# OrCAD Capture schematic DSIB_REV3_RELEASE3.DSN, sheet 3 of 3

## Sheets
3 Connectors: size Custom; title: dSIB; company: Intuitive Surgical, Inc.; note: TBD; note: 1266 Kifer Road; note: Sunnyvale, CA 94086
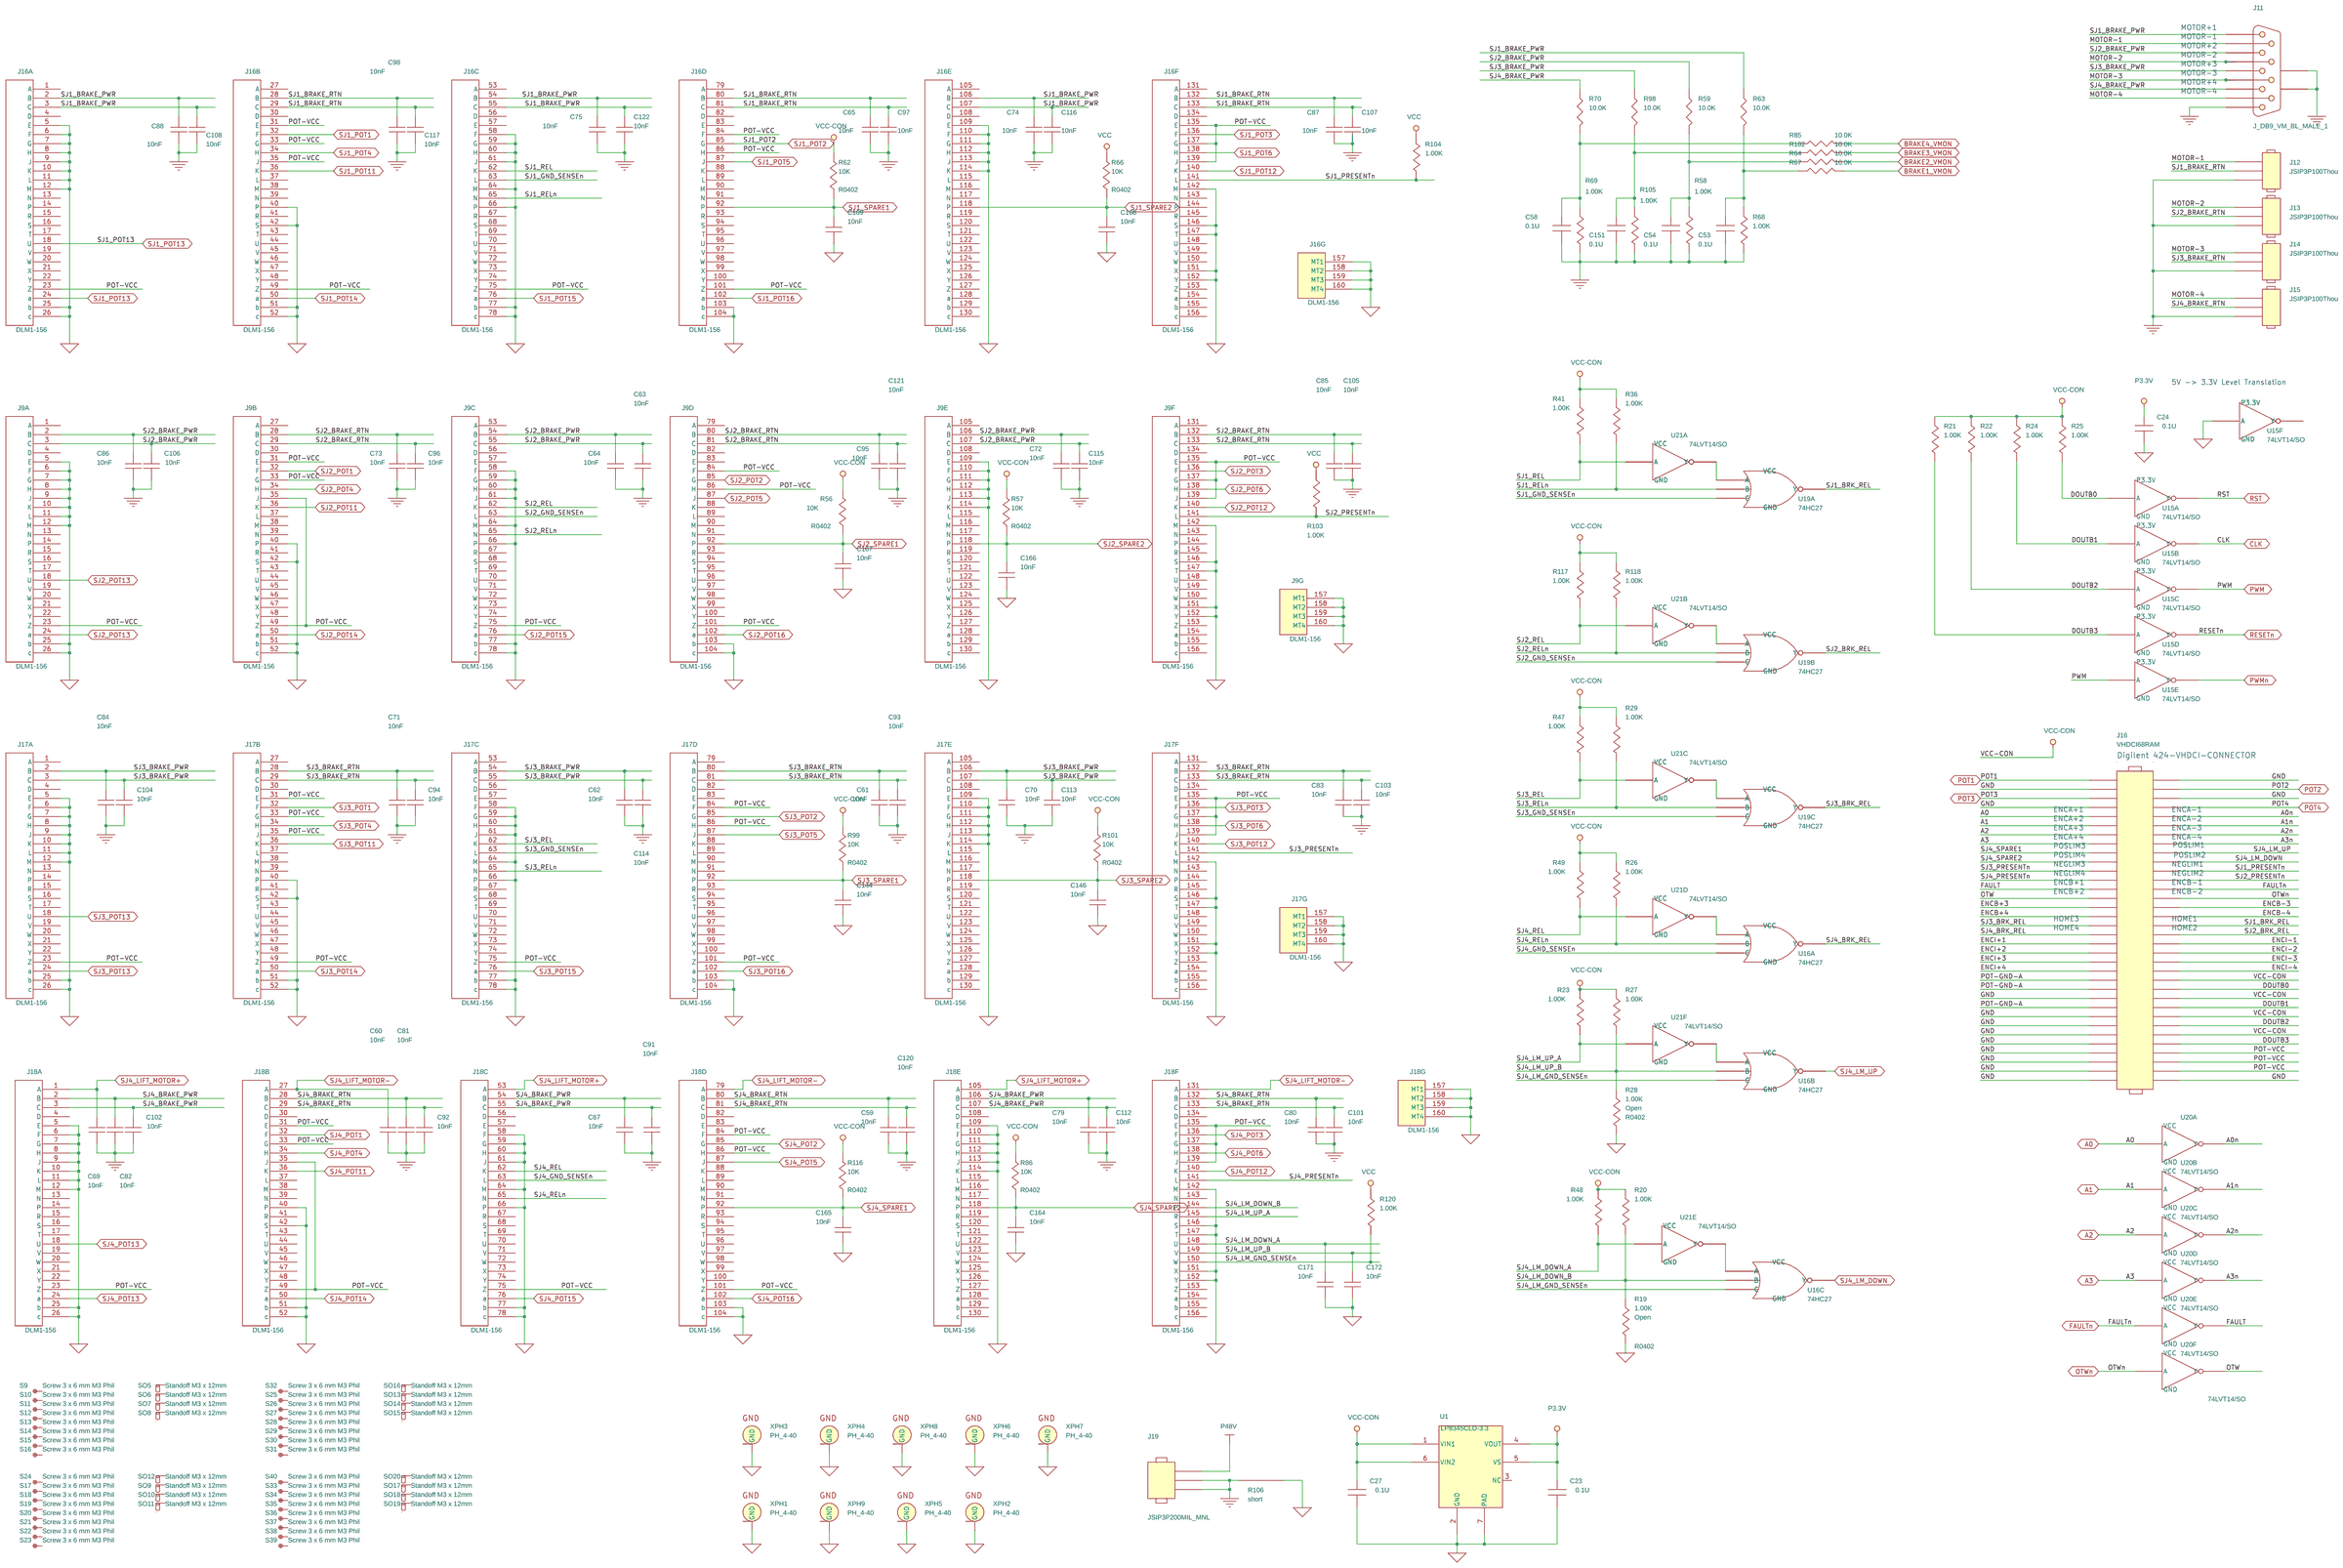
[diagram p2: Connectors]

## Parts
C23  0.1U  [C0402]
C24  0.1U  [C0402]
C27  0.1U  [C0402]
C53  0.1U  [C0402]
C54  0.1U  [C0402]
C58  0.1U  [C0402]
C59  10nF  [C0402]
C60  10nF  [C0402]
C61  10nF  [C0402]
C62  10nF  [C0402]
C63  10nF  [C0402]
C64  10nF  [C0402]
C65  10nF  [C0402]
C67  10nF  [C0402]
C69  10nF  [C0402]
C70  10nF  [C0402]
C71  10nF  [C0402]
C72  10nF  [C0402]
C73  10nF  [C0402]
C74  10nF  [C0402]
C75  10nF  [C0402]
C79  10nF  [C0402]
C80  10nF  [C0402]
C81  10nF  [C0402]
C82  10nF  [C0402]
C83  10nF  [C0402]
C84  10nF  [C0402]
C85  10nF  [C0402]
C86  10nF  [C0402]
C87  10nF  [C0402]
C88  10nF  [C0402]
C91  10nF  [C0402]
C92  10nF  [C0402]
C93  10nF  [C0402]
C94  10nF  [C0402]
C95  10nF  [C0402]
C96  10nF  [C0402]
C97  10nF  [C0402]
C98  10nF  [C0402]
C101  10nF  [C0402]
C102  10nF  [C0402]
C103  10nF  [C0402]
C104  10nF  [C0402]
C105  10nF  [C0402]
C106  10nF  [C0402]
C107  10nF  [C0402]
C108  10nF  [C0402]
C112  10nF  [C0402]
C113  10nF  [C0402]
C114  10nF  [C0402]
C115  10nF  [C0402]
C116  10nF  [C0402]
C117  10nF  [C0402]
C120  10nF  [C0402]
C121  10nF  [C0402]
C122  10nF  [C0402]
C144  10nF  [C0402]
C146  10nF  [C0402]
C151  0.1U  [C0402]
C164  10nF  [C0402]
C165  10nF  [C0402]
C166  10nF  [C0402]
C167  10nF  [C0402]
C168  10nF  [C0402]
C169  10nF  [C0402]
C171  10nF  [C0402]
C172  10nF  [C0402]
J9  DLM1-156  [DLM1-156]  (sections A,B,C,D,E,F,G)
J11  J_DB9_VM_BL_MALE_1  [DB9M]
J12  JSIP3P100Thou  [JSIP3P2.54MM]
J13  JSIP3P100Thou  [JSIP3P2.54MM]
J14  JSIP3P100Thou  [JSIP3P2.54MM]
J15  JSIP3P100Thou  [JSIP3P2.54MM]
J16  DLM1-156  [DLM1-156]  (sections A,B,C,D,E,F,G)
J17  DLM1-156  [DLM1-156]  (sections A,B,C,D,E,F,G)
J18  DLM1-156  [DLM1-156]  (sections A,B,C,D,E,F,G)
J19  JSIP3P200MIL_MNL  [TB-3/5.08]
R19  1.00K  [R0402]
R20  1.00K  [RESC1005_IS0402N]
R21  1.00K  [RESC1005_IS0402N]
R22  1.00K  [RESC1005_IS0402N]
R23  1.00K  [RESC1005_IS0402N]
R24  1.00K  [RESC1005_IS0402N]
R25  1.00K  [RESC1005_IS0402N]
R26  1.00K  [RESC1005_IS0402N]
R27  1.00K  [RESC1005_IS0402N]
R28  1.00K  [R0402]
R29  1.00K  [RESC1005_IS0402N]
R36  1.00K  [RESC1005_IS0402N]
R41  1.00K  [RESC1005_IS0402N]
R47  1.00K  [RESC1005_IS0402N]
R48  1.00K  [RESC1005_IS0402N]
R49  1.00K  [RESC1005_IS0402N]
R56  10K  [R0402]
R57  10K  [R0402]
R58  1.00K  [RESC1005_IS0402N]
R59  10.0K  [R0402]
R62  10K  [R0402]
R63  10.0K  [R0402]
R64  10.0K  [R0402]
R66  10K  [R0402]
R67  10.0K  [R0402]
R68  1.00K  [RESC1005_IS0402N]
R69  1.00K  [RESC1005_IS0402N]
R70  10.0K  [R0402]
R85  10.0K  [R0402]
R86  10K  [R0402]
R98  10.0K  [R0402]
R99  10K  [R0402]
R101  10K  [R0402]
R102  10.0K  [R0402]
R103  1.00K  [RESC1005_IS0402N]
R104  1.00K  [RESC1005_IS0402N]
R105  1.00K  [RESC1005_IS0402N]
R106  short  [S1210]
R116  10K  [R0402]
R117  1.00K  [RESC1005_IS0402N]
R118  1.00K  [RESC1005_IS0402N]
R120  1.00K  [RESC1005_IS0402N]
S9  Screw 3 x 6 mm M3 Phil  [TH825]
S10  Screw 3 x 6 mm M3 Phil  [TH825]
S11  Screw 3 x 6 mm M3 Phil  [TH825]
S12  Screw 3 x 6 mm M3 Phil  [TH825]
S13  Screw 3 x 6 mm M3 Phil  [TH825]
S14  Screw 3 x 6 mm M3 Phil  [TH825]
S15  Screw 3 x 6 mm M3 Phil  [TH825]
S16  Screw 3 x 6 mm M3 Phil  [TH825]
S17  Screw 3 x 6 mm M3 Phil  [TH825]
S18  Screw 3 x 6 mm M3 Phil  [TH825]
S19  Screw 3 x 6 mm M3 Phil  [TH825]
S20  Screw 3 x 6 mm M3 Phil  [TH825]
S21  Screw 3 x 6 mm M3 Phil  [TH825]
S22  Screw 3 x 6 mm M3 Phil  [TH825]
S23  Screw 3 x 6 mm M3 Phil  [TH825]
S24  Screw 3 x 6 mm M3 Phil  [TH825]
S25  Screw 3 x 6 mm M3 Phil  [TH825]
S26  Screw 3 x 6 mm M3 Phil  [TH825]
S27  Screw 3 x 6 mm M3 Phil  [TH825]
S28  Screw 3 x 6 mm M3 Phil  [TH825]
S29  Screw 3 x 6 mm M3 Phil  [TH825]
S30  Screw 3 x 6 mm M3 Phil  [TH825]
S31  Screw 3 x 6 mm M3 Phil  [TH825]
S32  Screw 3 x 6 mm M3 Phil  [TH825]
S33  Screw 3 x 6 mm M3 Phil  [TH825]
S34  Screw 3 x 6 mm M3 Phil  [TH825]
S35  Screw 3 x 6 mm M3 Phil  [TH825]
S36  Screw 3 x 6 mm M3 Phil  [TH825]
S37  Screw 3 x 6 mm M3 Phil  [TH825]
S38  Screw 3 x 6 mm M3 Phil  [TH825]
S39  Screw 3 x 6 mm M3 Phil  [TH825]
S40  Screw 3 x 6 mm M3 Phil  [TH825]
SO5  Standoff M3 x 12mm  [TH40Thou]
SO6  Standoff M3 x 12mm  [TH40Thou]
SO7  Standoff M3 x 12mm  [TH40Thou]
SO8  Standoff M3 x 12mm  [TH40Thou]
SO9  Standoff M3 x 12mm  [TH40Thou]
SO10  Standoff M3 x 12mm  [TH40Thou]
SO11  Standoff M3 x 12mm  [TH40Thou]
SO12  Standoff M3 x 12mm  [TH40Thou]
SO13  Standoff M3 x 12mm  [TH40Thou]
SO14  Standoff M3 x 12mm  [TH40Thou]
SO15  Standoff M3 x 12mm  [TH40Thou]
SO16  Standoff M3 x 12mm  [TH40Thou]
SO17  Standoff M3 x 12mm  [TH40Thou]
SO18  Standoff M3 x 12mm  [TH40Thou]
SO19  Standoff M3 x 12mm  [TH40Thou]
SO20  Standoff M3 x 12mm  [TH40Thou]
U1  LP8345CLD-3.3  [LLP6]
U15  74LVT14/SO  [TSSOP14]  (sections A,B,C,D,E,F)
U16  74HC27  [DHVQFN14]  (sections A,B,C)
U19  74HC27  [DHVQFN14]  (sections A,B,C)
U20  74LVT14/SO  [TSSOP14]  (sections A,B,C,D,E,F)
U21  74LVT14/SO  [TSSOP14]  (sections A,B,C,D,E,F)
XPH1  PH_4-40  [MTG120P]
XPH2  PH_4-40  [MTG120P]
XPH3  PH_4-40  [MTG120P]
XPH4  PH_4-40  [MTG120P]
XPH5  PH_4-40  [MTG120P]
XPH6  PH_4-40  [MTG120P]
XPH7  PH_4-40  [MTG120P]
XPH8  PH_4-40  [MTG120P]
XPH9  PH_4-40  [MTG120P]

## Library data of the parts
C23 = C_100nF_10%_50V_X7R_0: COMPFIXED: NO; COMPGROUP: 0; COMPHEIGHT: 0.000; COMPKEY: NO; COMPLOC: [6693.000,6327.000]; COMPLOCKED: NO; COMPROT: 180; COMPSIDE: BOT; DECOUPLER: NO; MEMORY: NO
C24 = C_100nF_10%_50V_X7R_0: COMPFIXED: NO; COMPGROUP: 0; COMPHEIGHT: 0.000; COMPKEY: NO; COMPLOC: [4590.000,6330.000]; COMPLOCKED: NO; COMPROT: 0; COMPSIDE: BOT; DECOUPLER: NO; FPLIST: C0603; MEMORY: NO
C27 = C_100nF_10%_50V_X7R_0: COMPFIXED: NO; COMPGROUP: 0; COMPHEIGHT: 0.000; COMPKEY: NO; COMPLOC: [6750.000,6096.000]; COMPLOCKED: NO; COMPROT: 0; COMPSIDE: BOT; DECOUPLER: NO; MEMORY: NO
C53 = C_100nF_10%_50V_X7R_0: COMPFIXED: NO; COMPGROUP: 0; COMPHEIGHT: 0.000; COMPKEY: NO; COMPLOC: [677.000,5735.000]; COMPLOCKED: NO; COMPROT: 0; COMPSIDE: BOT; DECOUPLER: NO; MEMORY: NO
C54 = C_100nF_10%_50V_X7R_0: COMPFIXED: NO; COMPGROUP: 0; COMPHEIGHT: 0.000; COMPKEY: NO; COMPLOC: [2005.000,5690.000]; COMPLOCKED: NO; COMPROT: 0; COMPSIDE: BOT; DECOUPLER: NO; MEMORY: NO
C58 = C_100nF_10%_50V_X7R_0: COMPFIXED: NO; COMPGROUP: 0; COMPHEIGHT: 0.000; COMPKEY: NO; COMPLOC: [5262.000,5310.000]; COMPLOCKED: NO; COMPROT: 0; COMPSIDE: BOT; DECOUPLER: NO; MEMORY: NO
C59 C144 C146 C164-C169 C171 C172 = C_10nF_100V_X7R_3: COMPFIXED: NO; COMPGROUP: 0; COMPHEIGHT: 0.000; COMPKEY: NO; COMPLOC: [4820.000,5170.000]; COMPLOCKED: NO; COMPROT: 180; COMPSIDE: BOT; DECOUPLER: NO; FPLIST: C0805; MEMORY: NO
C60 = C_10nF_100V_X7R_3: COMPFIXED: NO; COMPGROUP: 0; COMPHEIGHT: 0.000; COMPKEY: NO; COMPLOC: [4452.000,5172.000]; COMPLOCKED: NO; COMPROT: 0; COMPSIDE: BOT; DECOUPLER: NO; FPLIST: C0805; MEMORY: NO
C61 = C_10nF_100V_X7R_3: COMPFIXED: NO; COMPGROUP: 0; COMPHEIGHT: 0.000; COMPKEY: NO; COMPLOC: [3492.000,5178.000]; COMPLOCKED: NO; COMPROT: 0; COMPSIDE: BOT; DECOUPLER: NO; FPLIST: C0805; MEMORY: NO
C62 = C_10nF_100V_X7R_3: COMPFIXED: NO; COMPGROUP: 0; COMPHEIGHT: 0.000; COMPKEY: NO; COMPLOC: [3294.000,5178.000]; COMPLOCKED: NO; COMPROT: 0; COMPSIDE: BOT; DECOUPLER: NO; FPLIST: C0805; MEMORY: NO
C63 = C_10nF_100V_X7R_3: COMPFIXED: NO; COMPGROUP: 0; COMPHEIGHT: 0.000; COMPKEY: NO; COMPLOC: [2190.000,5148.000]; COMPLOCKED: NO; COMPROT: 270; COMPSIDE: BOT; DECOUPLER: NO; FPLIST: C0805; MEMORY: NO
C64 = C_10nF_100V_X7R_3: COMPFIXED: NO; COMPGROUP: 0; COMPHEIGHT: 0.000; COMPKEY: NO; COMPLOC: [2088.000,5148.000]; COMPLOCKED: NO; COMPROT: 270; COMPSIDE: BOT; DECOUPLER: NO; FPLIST: C0805; MEMORY: NO
C65 C74 C87 C88 C97 C107 C116 = C_10nF_100V_X7R_3: COMPFIXED: NO; COMPGROUP: 0; COMPHEIGHT: 0.000; COMPKEY: NO; COMPLOC: [675.000,4923.000]; COMPLOCKED: NO; COMPROT: 0; COMPSIDE: BOT; DECOUPLER: NO; MEMORY: NO
C67 = C_10nF_100V_X7R_3: COMPFIXED: NO; COMPGROUP: 0; COMPHEIGHT: 0.000; COMPKEY: NO; COMPLOC: [4182.000,5075.000]; COMPLOCKED: NO; COMPROT: 0; COMPSIDE: BOT; DECOUPLER: NO; FPLIST: C0805; MEMORY: NO
C69 = C_10nF_100V_X7R_3: COMPFIXED: NO; COMPGROUP: 0; COMPHEIGHT: 0.000; COMPKEY: NO; COMPLOC: [4182.000,5022.000]; COMPLOCKED: NO; COMPROT: 0; COMPSIDE: BOT; DECOUPLER: NO; FPLIST: C0805; MEMORY: NO
C70 = C_10nF_100V_X7R_3: COMPFIXED: NO; COMPGROUP: 0; COMPHEIGHT: 0.000; COMPKEY: NO; COMPLOC: [3768.000,4974.000]; COMPLOCKED: NO; COMPROT: 180; COMPSIDE: BOT; DECOUPLER: NO; FPLIST: C0805; MEMORY: NO
C71 = C_10nF_100V_X7R_3: COMPFIXED: NO; COMPGROUP: 0; COMPHEIGHT: 0.000; COMPKEY: NO; COMPLOC: [3048.000,4986.000]; COMPLOCKED: NO; COMPROT: 0; COMPSIDE: BOT; DECOUPLER: NO; FPLIST: C0805; MEMORY: NO
C72 = C_10nF_100V_X7R_3: COMPFIXED: NO; COMPGROUP: 0; COMPHEIGHT: 0.000; COMPKEY: NO; COMPLOC: [2520.000,4974.000]; COMPLOCKED: NO; COMPROT: 180; COMPSIDE: BOT; DECOUPLER: NO; FPLIST: C0805; MEMORY: NO
C73 = C_10nF_100V_X7R_3: COMPFIXED: NO; COMPGROUP: 0; COMPHEIGHT: 0.000; COMPKEY: NO; COMPLOC: [1794.000,4974.000]; COMPLOCKED: NO; COMPROT: 0; COMPSIDE: BOT; DECOUPLER: NO; FPLIST: C0805; MEMORY: NO
C75 = C_10nF_100V_X7R_3: COMPFIXED: NO; COMPGROUP: 0; COMPHEIGHT: 0.000; COMPKEY: NO; COMPLOC: [675.000,4977.000]; COMPLOCKED: NO; COMPROT: 0; COMPSIDE: BOT; DECOUPLER: NO; MEMORY: NO
C79 = C_10nF_100V_X7R_3: COMPFIXED: NO; COMPGROUP: 0; COMPHEIGHT: 0.000; COMPKEY: NO; COMPLOC: [4950.000,4968.000]; COMPLOCKED: NO; COMPROT: 180; COMPSIDE: BOT; DECOUPLER: NO; FPLIST: C0805; MEMORY: NO
C80 = C_10nF_100V_X7R_3: COMPFIXED: NO; COMPGROUP: 0; COMPHEIGHT: 0.000; COMPKEY: NO; COMPLOC: [4950.000,4920.000]; COMPLOCKED: NO; COMPROT: 180; COMPSIDE: BOT; DECOUPLER: NO; FPLIST: C0805; MEMORY: NO
C81 = C_10nF_100V_X7R_3: COMPFIXED: NO; COMPGROUP: 0; COMPHEIGHT: 0.000; COMPKEY: NO; COMPLOC: [4182.000,4968.000]; COMPLOCKED: NO; COMPROT: 0; COMPSIDE: BOT; DECOUPLER: NO; FPLIST: C0805; MEMORY: NO
C82 = C_10nF_100V_X7R_3: COMPFIXED: NO; COMPGROUP: 0; COMPHEIGHT: 0.000; COMPKEY: NO; COMPLOC: [4182.000,4920.000]; COMPLOCKED: NO; COMPROT: 0; COMPSIDE: BOT; DECOUPLER: NO; FPLIST: C0805; MEMORY: NO
C83 = C_10nF_100V_X7R_3: COMPFIXED: NO; COMPGROUP: 0; COMPHEIGHT: 0.000; COMPKEY: NO; COMPLOC: [3768.000,4920.000]; COMPLOCKED: NO; COMPROT: 180; COMPSIDE: BOT; DECOUPLER: NO; FPLIST: C0805; MEMORY: NO
C84 = C_10nF_100V_X7R_3: COMPFIXED: NO; COMPGROUP: 0; COMPHEIGHT: 0.000; COMPKEY: NO; COMPLOC: [3048.000,4932.000]; COMPLOCKED: NO; COMPROT: 0; COMPSIDE: BOT; DECOUPLER: NO; FPLIST: C0805; MEMORY: NO
C85 = C_10nF_100V_X7R_3: COMPFIXED: NO; COMPGROUP: 0; COMPHEIGHT: 0.000; COMPKEY: NO; COMPLOC: [2520.000,4920.000]; COMPLOCKED: NO; COMPROT: 180; COMPSIDE: BOT; DECOUPLER: NO; FPLIST: C0805; MEMORY: NO
C86 = C_10nF_100V_X7R_3: COMPFIXED: NO; COMPGROUP: 0; COMPHEIGHT: 0.000; COMPKEY: NO; COMPLOC: [1794.000,4920.000]; COMPLOCKED: NO; COMPROT: 0; COMPSIDE: BOT; DECOUPLER: NO; FPLIST: C0805; MEMORY: NO
C91 = C_10nF_100V_X7R_3: COMPFIXED: NO; COMPGROUP: 0; COMPHEIGHT: 0.000; COMPKEY: NO; COMPLOC: [4950.000,4872.000]; COMPLOCKED: NO; COMPROT: 180; COMPSIDE: BOT; DECOUPLER: NO; FPLIST: C0805; MEMORY: NO
C92 = C_10nF_100V_X7R_3: COMPFIXED: NO; COMPGROUP: 0; COMPHEIGHT: 0.000; COMPKEY: NO; COMPLOC: [4182.000,4872.000]; COMPLOCKED: NO; COMPROT: 0; COMPSIDE: BOT; DECOUPLER: NO; FPLIST: C0805; MEMORY: NO
C93 = C_10nF_100V_X7R_3: COMPFIXED: NO; COMPGROUP: 0; COMPHEIGHT: 0.000; COMPKEY: NO; COMPLOC: [3768.000,4872.000]; COMPLOCKED: NO; COMPROT: 180; COMPSIDE: BOT; DECOUPLER: NO; FPLIST: C0805; MEMORY: NO
C94 = C_10nF_100V_X7R_3: COMPFIXED: NO; COMPGROUP: 0; COMPHEIGHT: 0.000; COMPKEY: NO; COMPLOC: [3048.000,4878.000]; COMPLOCKED: NO; COMPROT: 0; COMPSIDE: BOT; DECOUPLER: NO; FPLIST: C0805; MEMORY: NO
C95 = C_10nF_100V_X7R_3: COMPFIXED: NO; COMPGROUP: 0; COMPHEIGHT: 0.000; COMPKEY: NO; COMPLOC: [2520.000,4866.000]; COMPLOCKED: NO; COMPROT: 180; COMPSIDE: BOT; DECOUPLER: NO; FPLIST: C0805; MEMORY: NO
C96 = C_10nF_100V_X7R_3: COMPFIXED: NO; COMPGROUP: 0; COMPHEIGHT: 0.000; COMPKEY: NO; COMPLOC: [1794.000,4872.000]; COMPLOCKED: NO; COMPROT: 0; COMPSIDE: BOT; DECOUPLER: NO; FPLIST: C0805; MEMORY: NO
C98 = C_10nF_100V_X7R_3: COMPFIXED: NO; COMPGROUP: 0; COMPHEIGHT: 0.000; COMPKEY: NO; COMPLOC: [675.000,4869.000]; COMPLOCKED: NO; COMPROT: 0; COMPSIDE: BOT; DECOUPLER: NO; MEMORY: NO
C101 = C_10nF_100V_X7R_3: COMPFIXED: NO; COMPGROUP: 0; COMPHEIGHT: 0.000; COMPKEY: NO; COMPLOC: [4950.000,4818.000]; COMPLOCKED: NO; COMPROT: 180; COMPSIDE: BOT; DECOUPLER: NO; FPLIST: C0805; MEMORY: NO
C102 = C_10nF_100V_X7R_3: COMPFIXED: NO; COMPGROUP: 0; COMPHEIGHT: 0.000; COMPKEY: NO; COMPLOC: [4182.000,4818.000]; COMPLOCKED: NO; COMPROT: 0; COMPSIDE: BOT; DECOUPLER: NO; FPLIST: C0805; MEMORY: NO
C103 = C_10nF_100V_X7R_3: COMPFIXED: NO; COMPGROUP: 0; COMPHEIGHT: 0.000; COMPKEY: NO; COMPLOC: [3768.000,4818.000]; COMPLOCKED: NO; COMPROT: 180; COMPSIDE: BOT; DECOUPLER: NO; FPLIST: C0805; MEMORY: NO
C104 = C_10nF_100V_X7R_3: COMPFIXED: NO; COMPGROUP: 0; COMPHEIGHT: 0.000; COMPKEY: NO; COMPLOC: [3048.000,4824.000]; COMPLOCKED: NO; COMPROT: 0; COMPSIDE: BOT; DECOUPLER: NO; FPLIST: C0805; MEMORY: NO
C105 = C_10nF_100V_X7R_3: COMPFIXED: NO; COMPGROUP: 0; COMPHEIGHT: 0.000; COMPKEY: NO; COMPLOC: [2520.000,4812.000]; COMPLOCKED: NO; COMPROT: 180; COMPSIDE: BOT; DECOUPLER: NO; FPLIST: C0805; MEMORY: NO
C106 = C_10nF_100V_X7R_3: COMPFIXED: NO; COMPGROUP: 0; COMPHEIGHT: 0.000; COMPKEY: NO; COMPLOC: [1794.000,4818.000]; COMPLOCKED: NO; COMPROT: 0; COMPSIDE: BOT; DECOUPLER: NO; FPLIST: C0805; MEMORY: NO
C108 = C_10nF_100V_X7R_3: COMPFIXED: NO; COMPGROUP: 0; COMPHEIGHT: 0.000; COMPKEY: NO; COMPLOC: [675.000,4821.000]; COMPLOCKED: NO; COMPROT: 0; COMPSIDE: BOT; DECOUPLER: NO; MEMORY: NO
C112 = C_10nF_100V_X7R_3: COMPFIXED: NO; COMPGROUP: 0; COMPHEIGHT: 0.000; COMPKEY: NO; COMPLOC: [4950.000,4770.000]; COMPLOCKED: NO; COMPROT: 180; COMPSIDE: BOT; DECOUPLER: NO; FPLIST: C0805; MEMORY: NO
C113 = C_10nF_100V_X7R_3: COMPFIXED: NO; COMPGROUP: 0; COMPHEIGHT: 0.000; COMPKEY: NO; COMPLOC: [3768.000,4764.000]; COMPLOCKED: NO; COMPROT: 180; COMPSIDE: BOT; DECOUPLER: NO; FPLIST: C0805; MEMORY: NO
C114 = C_10nF_100V_X7R_3: COMPFIXED: NO; COMPGROUP: 0; COMPHEIGHT: 0.000; COMPKEY: NO; COMPLOC: [3048.000,4770.000]; COMPLOCKED: NO; COMPROT: 0; COMPSIDE: BOT; DECOUPLER: NO; FPLIST: C0805; MEMORY: NO
C115 = C_10nF_100V_X7R_3: COMPFIXED: NO; COMPGROUP: 0; COMPHEIGHT: 0.000; COMPKEY: NO; COMPLOC: [2520.000,4758.000]; COMPLOCKED: NO; COMPROT: 180; COMPSIDE: BOT; DECOUPLER: NO; FPLIST: C0805; MEMORY: NO
C117 = C_10nF_100V_X7R_3: COMPFIXED: NO; COMPGROUP: 0; COMPHEIGHT: 0.000; COMPKEY: NO; COMPLOC: [675.000,4765.000]; COMPLOCKED: NO; COMPROT: 0; COMPSIDE: BOT; DECOUPLER: NO; MEMORY: NO
C120 = C_10nF_100V_X7R_3: COMPFIXED: NO; COMPGROUP: 0; COMPHEIGHT: 0.000; COMPKEY: NO; COMPLOC: [4950.000,4668.000]; COMPLOCKED: NO; COMPROT: 180; COMPSIDE: BOT; DECOUPLER: NO; FPLIST: C0805; MEMORY: NO
C121 = C_10nF_100V_X7R_3: COMPFIXED: NO; COMPGROUP: 0; COMPHEIGHT: 0.000; COMPKEY: NO; COMPLOC: [2520.000,4704.000]; COMPLOCKED: NO; COMPROT: 180; COMPSIDE: BOT; DECOUPLER: NO; FPLIST: C0805; MEMORY: NO
C122 = C_10nF_100V_X7R_3: COMPFIXED: NO; COMPGROUP: 0; COMPHEIGHT: 0.000; COMPKEY: NO; COMPLOC: [672.000,4674.000]; COMPLOCKED: NO; COMPROT: 0; COMPSIDE: BOT; DECOUPLER: NO; MEMORY: NO
C151 = C_100nF_10%_50V_X7R_0: COMPFIXED: NO; COMPGROUP: 0; COMPHEIGHT: 0.000; COMPKEY: NO; COMPLOC: [5490.000,3960.000]; COMPLOCKED: NO; COMPROT: 180; COMPSIDE: BOT; DECOUPLER: NO; MEMORY: NO
J9 = DLM1-156_0: COMPFIXED: YES; COMPGROUP: 0; COMPHEIGHT: 0.000; COMPKEY: NO; COMPLOC: [2190.000,3498.000]; COMPLOCKED: NO; COMPROT: 270; COMPSIDE: TOP; DECOUPLER: NO; MEMORY: NO
J11 = J_DB9_VM_BL_MALE_1: COMPFIXED: YES; COMPGROUP: 0; COMPHEIGHT: 0.000; COMPKEY: NO; COMPLOC: [6000.000,6500.000]; COMPLOCKED: YES; COMPROT: 0; COMPSIDE: BOT; DECOUPLER: NO; FPLIST: DB9M48,DB9M; MEMORY: NO; Vendor P/N: 626-1020-ND
J12 J13 = JSIP3P100Thou: COMPFIXED: NO; COMPGROUP: 0; COMPHEIGHT: 0.000; COMPKEY: NO; COMPLOC: [6400.000,5900.000]; COMPLOCKED: NO; COMPROT: 90; COMPSIDE: TOP; DECOUPLER: NO; MEMORY: NO; MFG: Wurth; MFG P/N: 61300311121; Vendor P/N: 732-5316-ND
J14 = JSIP3P100Thou: COMPFIXED: NO; COMPGROUP: 0; COMPHEIGHT: 0.000; COMPKEY: NO; COMPLOC: [6500.000,5900.000]; COMPLOCKED: NO; COMPROT: 90; COMPSIDE: TOP; DECOUPLER: NO; MEMORY: NO; MFG: Wurth; MFG P/N: 61300311121; Vendor P/N: 732-5316-ND
J15 = JSIP3P100Thou: COMPFIXED: NO; COMPGROUP: 0; COMPHEIGHT: 0.000; COMPKEY: NO; COMPLOC: [6600.000,5900.000]; COMPLOCKED: NO; COMPROT: 90; COMPSIDE: TOP; DECOUPLER: NO; MEMORY: NO; MFG: Wurth; MFG P/N: 61300311121; Vendor P/N: 732-5316-ND
J16 = DLM1-156_0: COMPFIXED: YES; COMPGROUP: 0; COMPHEIGHT: 0.000; COMPKEY: NO; COMPLOC: [1000.000,3500.000]; COMPLOCKED: NO; COMPROT: 270; COMPSIDE: TOP; DECOUPLER: NO; FPLIST: DLM1-156_FIXED,DLM1-156; MEMORY: NO; MFG P/N: R-HI-008068-2
J17 = DLM1-156_0: COMPFIXED: YES; COMPGROUP: 0; COMPHEIGHT: 0.000; COMPKEY: NO; COMPLOC: [3390.000,3498.000]; COMPLOCKED: NO; COMPROT: 270; COMPSIDE: TOP; DECOUPLER: NO; FPLIST: DLM1-156_FIXED,DLM1-156; MEMORY: NO
J18 = DLM1-156_0: COMPFIXED: YES; COMPGROUP: 0; COMPHEIGHT: 0.000; COMPKEY: NO; COMPLOC: [4605.000,3495.000]; COMPLOCKED: NO; COMPROT: 270; COMPSIDE: TOP; DECOUPLER: NO; MEMORY: NO
J19 = JSIP_3P_200MIL_RAM_MNL: COMPFIXED: NO; COMPGROUP: 0; COMPHEIGHT: 0.000; COMPKEY: NO; COMPLOC: [6012.000,3780.000]; COMPLOCKED: NO; COMPROT: 0; COMPSIDE: TOP; DECOUPLER: NO; MEMORY: NO
R19 = R1K1%0402_0: COMPFIXED: NO; COMPGROUP: 0; COMPHEIGHT: 0.000; COMPKEY: NO; COMPLOC: [4120.000,6615.000]; COMPLOCKED: NO; COMPROT: 0; COMPSIDE: BOT; DECOUPLER: NO; ISI P/N: Open; MEMORY: NO
R20 = R1K1%0402_0: COMPFIXED: NO; COMPGROUP: 0; COMPHEIGHT: 0.000; COMPKEY: NO; COMPLOC: [3978.000,6565.000]; COMPLOCKED: NO; COMPROT: 180; COMPSIDE: BOT; DECOUPLER: NO; FPLIST: R0402; MEMORY: NO
R21 = R1K1%0402_0: COMPFIXED: NO; COMPGROUP: 0; COMPHEIGHT: 0.000; COMPKEY: NO; COMPLOC: [4678.000,6515.000]; COMPLOCKED: NO; COMPROT: 180; COMPSIDE: BOT; DECOUPLER: NO; FPLIST: R0402; MEMORY: NO
R22 = R1K1%0402_0: COMPFIXED: NO; COMPGROUP: 0; COMPHEIGHT: 0.000; COMPKEY: NO; COMPLOC: [4267.000,6495.000]; COMPLOCKED: NO; COMPROT: 0; COMPSIDE: BOT; DECOUPLER: NO; FPLIST: R0402; MEMORY: NO
R23 = R1K1%0402_0: COMPFIXED: NO; COMPGROUP: 0; COMPHEIGHT: 0.000; COMPKEY: NO; COMPLOC: [4678.000,6415.000]; COMPLOCKED: NO; COMPROT: 180; COMPSIDE: BOT; DECOUPLER: NO; FPLIST: R0402; MEMORY: NO
R24 = R1K1%0402_0: COMPFIXED: NO; COMPGROUP: 0; COMPHEIGHT: 0.000; COMPKEY: NO; COMPLOC: [4267.000,6440.000]; COMPLOCKED: NO; COMPROT: 0; COMPSIDE: BOT; DECOUPLER: NO; FPLIST: R0402; MEMORY: NO
R25 = R1K1%0402_0: COMPFIXED: NO; COMPGROUP: 0; COMPHEIGHT: 0.000; COMPKEY: NO; COMPLOC: [4267.000,6385.000]; COMPLOCKED: NO; COMPROT: 0; COMPSIDE: BOT; DECOUPLER: NO; FPLIST: R0402; MEMORY: NO
R26 = R1K1%0402_0: COMPFIXED: NO; COMPGROUP: 0; COMPHEIGHT: 0.000; COMPKEY: NO; COMPLOC: [4050.000,6322.000]; COMPLOCKED: NO; COMPROT: 90; COMPSIDE: BOT; DECOUPLER: NO; FPLIST: R0402; MEMORY: NO
R27 = R1K1%0402_0: COMPFIXED: NO; COMPGROUP: 0; COMPHEIGHT: 0.000; COMPKEY: NO; COMPLOC: [3995.000,6322.000]; COMPLOCKED: NO; COMPROT: 90; COMPSIDE: BOT; DECOUPLER: NO; FPLIST: R0402; MEMORY: NO
R28 = R1K1%0402_0: COMPFIXED: NO; COMPGROUP: 0; COMPHEIGHT: 0.000; COMPKEY: NO; COMPLOC: [3870.000,6320.000]; COMPLOCKED: NO; COMPROT: 180; COMPSIDE: BOT; DECOUPLER: NO; ISI P/N: Open; MEMORY: NO
R29 = R1K1%0402_0: COMPFIXED: NO; COMPGROUP: 0; COMPHEIGHT: 0.000; COMPKEY: NO; COMPLOC: [4312.000,6215.000]; COMPLOCKED: NO; COMPROT: 0; COMPSIDE: BOT; DECOUPLER: NO; FPLIST: R0402; MEMORY: NO
R36 R41 = R1K1%0402_0: COMPFIXED: NO; COMPGROUP: 0; COMPHEIGHT: 0.000; COMPKEY: NO; COMPLOC: [5113.000,5930.000]; COMPLOCKED: NO; COMPROT: 180; COMPSIDE: BOT; DECOUPLER: NO; FPLIST: R0402; MEMORY: NO
R47 = R1K1%0402_0: COMPFIXED: NO; COMPGROUP: 0; COMPHEIGHT: 0.000; COMPKEY: NO; COMPLOC: [5113.000,5835.000]; COMPLOCKED: NO; COMPROT: 180; COMPSIDE: BOT; DECOUPLER: NO; FPLIST: R0402; MEMORY: NO
R48 = R1K1%0402_0: COMPFIXED: NO; COMPGROUP: 0; COMPHEIGHT: 0.000; COMPKEY: NO; COMPLOC: [4697.000,5860.000]; COMPLOCKED: NO; COMPROT: 0; COMPSIDE: BOT; DECOUPLER: NO; FPLIST: R0402; MEMORY: NO
R49 = R1K1%0402_0: COMPFIXED: NO; COMPGROUP: 0; COMPHEIGHT: 0.000; COMPKEY: NO; COMPLOC: [4697.000,5805.000]; COMPLOCKED: NO; COMPROT: 0; COMPSIDE: BOT; DECOUPLER: NO; FPLIST: R0402; MEMORY: NO
R56 R57 R62 R66 R86 R99 R101 R116 = R10.0K1%0402_0: COMPFIXED: NO; COMPGROUP: 0; COMPHEIGHT: 0.000; COMPKEY: NO; COMPLOC: [2058.000,5802.000]; COMPLOCKED: NO; COMPROT: 180; COMPSIDE: BOT; DECOUPLER: NO; MEMORY: NO
R58 = R1K1%0402_0: COMPFIXED: NO; COMPGROUP: 0; COMPHEIGHT: 0.000; COMPKEY: NO; COMPLOC: [1963.000,5745.000]; COMPLOCKED: NO; COMPROT: 180; COMPSIDE: BOT; DECOUPLER: NO; MEMORY: NO
R59 = R_10K_1%_TF_0402: COMPFIXED: NO; COMPGROUP: 0; COMPHEIGHT: 0.000; COMPKEY: NO; COMPLOC: [1962.000,5802.000]; COMPLOCKED: NO; COMPROT: 180; COMPSIDE: BOT; DECOUPLER: NO; MEMORY: NO
R63 = R_10K_1%_TF_0402: COMPFIXED: NO; COMPGROUP: 0; COMPHEIGHT: 0.000; COMPKEY: NO; COMPLOC: [635.000,5795.000]; COMPLOCKED: NO; COMPROT: 180; COMPSIDE: BOT; DECOUPLER: NO; MEMORY: NO
R64 = R_10K_1%_TF_0402: COMPFIXED: NO; COMPGROUP: 0; COMPHEIGHT: 0.000; COMPKEY: NO; COMPLOC: [2058.000,5694.000]; COMPLOCKED: NO; COMPROT: 180; COMPSIDE: BOT; DECOUPLER: NO; MEMORY: NO
R67 = R_10K_1%_TF_0402: COMPFIXED: NO; COMPGROUP: 0; COMPHEIGHT: 0.000; COMPKEY: NO; COMPLOC: [786.000,5670.000]; COMPLOCKED: NO; COMPROT: 180; COMPSIDE: BOT; DECOUPLER: NO; MEMORY: NO
R68 = R1K1%0402_0: COMPFIXED: NO; COMPGROUP: 0; COMPHEIGHT: 0.000; COMPKEY: NO; COMPLOC: [633.000,5680.000]; COMPLOCKED: NO; COMPROT: 180; COMPSIDE: BOT; DECOUPLER: NO; MEMORY: NO
R69 = R1K1%0402_0: COMPFIXED: NO; COMPGROUP: 0; COMPHEIGHT: 0.000; COMPKEY: NO; COMPLOC: [5218.000,5360.000]; COMPLOCKED: NO; COMPROT: 180; COMPSIDE: BOT; DECOUPLER: NO; MEMORY: NO
R70 = R_10K_1%_TF_0402: COMPFIXED: NO; COMPGROUP: 0; COMPHEIGHT: 0.000; COMPKEY: NO; COMPLOC: [5262.000,5256.000]; COMPLOCKED: NO; COMPROT: 0; COMPSIDE: BOT; DECOUPLER: NO; MEMORY: NO
R85 = R_10K_1%_TF_0402: COMPFIXED: NO; COMPGROUP: 0; COMPHEIGHT: 0.000; COMPKEY: NO; COMPLOC: [5610.000,4590.000]; COMPLOCKED: NO; COMPROT: 0; COMPSIDE: BOT; DECOUPLER: NO; MEMORY: NO
R98 = R_10K_1%_TF_0402: COMPFIXED: NO; COMPGROUP: 0; COMPHEIGHT: 0.000; COMPKEY: NO; COMPLOC: [5493.000,4071.000]; COMPLOCKED: NO; COMPROT: 180; COMPSIDE: BOT; DECOUPLER: NO; MEMORY: NO
R102 = R_10K_1%_TF_0402: COMPFIXED: NO; COMPGROUP: 0; COMPHEIGHT: 0.000; COMPKEY: NO; COMPLOC: [5490.000,4014.000]; COMPLOCKED: NO; COMPROT: 180; COMPSIDE: BOT; DECOUPLER: NO; MEMORY: NO
R103 = R1K1%0402_0: COMPFIXED: NO; COMPGROUP: 0; COMPHEIGHT: 0.000; COMPKEY: NO; COMPLOC: [2513.000,4025.000]; COMPLOCKED: NO; COMPROT: 180; COMPSIDE: BOT; DECOUPLER: NO; FPLIST: R0402; MEMORY: NO
R104 = R1K1%0402_0: COMPFIXED: NO; COMPGROUP: 0; COMPHEIGHT: 0.000; COMPKEY: NO; COMPLOC: [1408.000,4025.000]; COMPLOCKED: NO; COMPROT: 180; COMPSIDE: BOT; DECOUPLER: NO; FPLIST: R0402; MEMORY: NO
R105 = R1K1%0402_0: COMPFIXED: NO; COMPGROUP: 0; COMPHEIGHT: 0.000; COMPKEY: NO; COMPLOC: [5532.000,3905.000]; COMPLOCKED: NO; COMPROT: 0; COMPSIDE: BOT; DECOUPLER: NO; MEMORY: NO
R106 = R_SHORT_1: COMPFIXED: NO; COMPGROUP: 0; COMPHEIGHT: 0.000; COMPKEY: NO; COMPLOC: [5612.500,3777.500]; COMPLOCKED: NO; COMPROT: 270; COMPSIDE: BOT; DECOUPLER: NO; MEMORY: NO
R117 = R1K1%0402_0: COMPFIXED: NO; COMPGROUP: 0; COMPHEIGHT: 0.000; COMPKEY: NO; COMPLOC: [3275.000,3312.000]; COMPLOCKED: NO; COMPROT: 90; COMPSIDE: BOT; DECOUPLER: NO; FPLIST: R0402; MEMORY: NO
R118 = R1K1%0402_0: COMPFIXED: NO; COMPGROUP: 0; COMPHEIGHT: 0.000; COMPKEY: NO; COMPLOC: [3220.000,3312.000]; COMPLOCKED: NO; COMPROT: 90; COMPSIDE: BOT; DECOUPLER: NO; FPLIST: R0402; MEMORY: NO
R120 = R1K1%0402_0: COMPFIXED: NO; COMPGROUP: 0; COMPHEIGHT: 0.000; COMPKEY: NO; COMPLOC: [4993.000,2575.000]; COMPLOCKED: NO; COMPROT: 180; COMPSIDE: BOT; DECOUPLER: NO; FPLIST: R0402; MEMORY: NO
S9-S40 = M3_1
SO5-SO20 = Standoff_M3_12mm_1
U1 = UREG_LP38691_3.3V_0.5A_LDO: COMPFIXED: NO; COMPGROUP: 0; COMPHEIGHT: 0.000; COMPKEY: NO; COMPLOC: [6762.000,6156.000]; COMPLOCKED: NO; COMPROT: 0; COMPSIDE: BOT; DECOUPLER: NO; MEMORY: NO
U15 = U_74LVT14_TSSOP14: COMPFIXED: NO; COMPGROUP: 0; COMPHEIGHT: 0.000; COMPKEY: NO; COMPLOC: [4359.000,6387.000]; COMPLOCKED: NO; COMPROT: 270; COMPSIDE: BOT; DECOUPLER: NO; MEMORY: NO
U16 = U_74HC27_DHVQFN14: COMPFIXED: NO; COMPGROUP: 0; COMPHEIGHT: 0.000; COMPKEY: NO; COMPLOC: [4038.000,6396.000]; COMPLOCKED: NO; COMPROT: 0; COMPSIDE: BOT; DECOUPLER: NO; MEMORY: NO
U19 = U_74HC27_DHVQFN14: COMPFIXED: NO; COMPGROUP: 0; COMPHEIGHT: 0.000; COMPKEY: NO; COMPLOC: [4374.000,6060.000]; COMPLOCKED: NO; COMPROT: 0; COMPSIDE: BOT; DECOUPLER: NO; MEMORY: NO
U20 = 74HCT14_0: COMPFIXED: NO; COMPGROUP: 0; COMPHEIGHT: 0.000; COMPKEY: NO; COMPLOC: [3355.000,6225.000]; COMPLOCKED: NO; COMPROT: 90; COMPSIDE: BOT; DECOUPLER: NO; MEMORY: NO
U21 = 74HCT14_0: COMPFIXED: NO; COMPGROUP: 0; COMPHEIGHT: 0.000; COMPKEY: NO; COMPLOC: [5022.000,5934.000]; COMPLOCKED: NO; COMPROT: 90; COMPSIDE: BOT; DECOUPLER: NO; MEMORY: NO
XPH1 = 135006_GND_Plated_Hole_120_mil: COMPFIXED: NO; COMPGROUP: 0; COMPHEIGHT: 0.000; COMPKEY: NO; COMPLOC: [318.000,6755.000]; COMPLOCKED: NO; COMPROT: 0; COMPSIDE: TOP; DECOUPLER: NO; MEMORY: NO
XPH2 = 135006_GND_Plated_Hole_120_mil: COMPFIXED: NO; COMPGROUP: 0; COMPHEIGHT: 0.000; COMPKEY: NO; COMPLOC: [1968.000,6755.000]; COMPLOCKED: NO; COMPROT: 0; COMPSIDE: TOP; DECOUPLER: NO; MEMORY: NO
XPH3 = 135006_GND_Plated_Hole_120_mil: COMPFIXED: NO; COMPGROUP: 0; COMPHEIGHT: 0.000; COMPKEY: NO; COMPLOC: [3968.000,6755.000]; COMPLOCKED: YES; COMPROT: 0; COMPSIDE: TOP; DECOUPLER: NO; MEMORY: NO
XPH4 = 135006_GND_Plated_Hole_120_mil: COMPFIXED: YES; COMPGROUP: 0; COMPHEIGHT: 0.000; COMPKEY: NO; COMPLOC: [5168.000,6755.000]; COMPLOCKED: YES; COMPROT: 0; COMPSIDE: TOP; DECOUPLER: NO; MEMORY: NO
XPH5 = 135006_GND_Plated_Hole_120_mil: COMPFIXED: YES; COMPGROUP: 0; COMPHEIGHT: 0.000; COMPKEY: NO; COMPLOC: [6818.000,6755.000]; COMPLOCKED: YES; COMPROT: 0; COMPSIDE: TOP; DECOUPLER: NO; MEMORY: NO
XPH6 = 135006_GND_Plated_Hole_120_mil: COMPFIXED: YES; COMPGROUP: 0; COMPHEIGHT: 0.000; COMPKEY: NO; COMPLOC: [318.000,4755.000]; COMPLOCKED: YES; COMPROT: 0; COMPSIDE: TOP; DECOUPLER: NO; MEMORY: NO
XPH7 = 135006_GND_Plated_Hole_120_mil: COMPFIXED: YES; COMPGROUP: 0; COMPHEIGHT: 0.000; COMPKEY: NO; COMPLOC: [6818.000,4705.000]; COMPLOCKED: YES; COMPROT: 0; COMPSIDE: TOP; DECOUPLER: NO; MEMORY: NO
XPH8 = 135006_GND_Plated_Hole_120_mil: COMPFIXED: YES; COMPGROUP: 0; COMPHEIGHT: 0.000; COMPKEY: NO; COMPLOC: [318.000,2355.000]; COMPLOCKED: YES; COMPROT: 0; COMPSIDE: TOP; DECOUPLER: NO; MEMORY: NO
XPH9 = 135006_GND_Plated_Hole_120_mil: COMPFIXED: YES; COMPGROUP: 0; COMPHEIGHT: 0.000; COMPKEY: NO; COMPLOC: [6818.000,2355.000]; COMPLOCKED: YES; COMPROT: 0; COMPSIDE: TOP; DECOUPLER: NO; MEMORY: NO

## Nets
GND: C23.2 C24.2 C27.1 C27.2 C65.1 C74.1 C75.1 C87.1 C88.1 C97.1 C98.1 C107.1 C108.1 C116.1 C117.1 C122.1 C144.2 C146.2 C164.2 C165.2 C166.2 C167.2 C168.2 C169.2 C171.2 C172.2 J9.5(E) J9.6(F) J9.7(G) J9.8(H) J9.9(J) J9.10(K) J9.11(L) J9.12(M) J9.23(Z) J9.25(b) J9.26(c) J9.31(E) J9.33(G) J9.35(J) J9.40(P) J9.42(S) J9.49(Z) J9.51(b) J9.52(c) J9.58(F) J9.59(G) J9.60(H) J9.61(J) J9.64(M) J9.66(P) J9.75(Z) J9.77(b) J9.78(c) J9.84(F) J9.86(H) J9.101(Z) J9.103(b) J9.104(c) J9.109(E) J9.110(F) J9.111(G) J9.112(H) J9.113(J) J9.114(K) J9.135(E) J9.137(G) J9.139(J) J9.141(L) J9.142(M) J9.146(S) J9.147(T) J9.151(X) J9.152(Y) J9.157(MT1) J9.158(MT2) J9.159(MT3) J9.160(MT4) J11.1 J12.2 J16.1 J16.2 J16.3 J16.5 J16.6 J16.7 J16.8 J16.9 J16.10 J16.11 J16.12 J16.23 J16.25 J16.26 J16.27(A) J16.28(B) J16.29(C) J16.31(E) J16.32(F) J16.33(G) J16.34(H) J16.35(J) J16.36(K) J16.38(M) J16.40(P) J16.42(S) J16.49(Z) J16.51(b) J16.52(c) J16.54(B) J16.55(C) J16.57(E) J16.58(F) J16.59(G) J16.60(H) J16.61(J) J16.62(K) J16.63(L) J16.64(M) J16.65(N) J16.66(P) J16.67(R) J16.68(S) J16.75(Z) J16.77(b) J16.78(c) J16.80(B) J16.81(C) J16.84(F) J16.86(H) J16.101(Z) J16.103(b) J16.104(c) J16.106(B) J16.107(C) J16.109(E) J16.110(F) J16.111(G) J16.112(H) J16.113(J) J16.114(K) J16.132(B) J16.133(C) J16.135(E) J16.137(G) J16.139(J) J16.141(L) J16.142(M) J16.146(S) J16.147(T) J16.151(X) J16.152(Y) J16.157(MT1) J16.158(MT2) J16.159(MT3) J16.160(MT4) J17.5(E) J17.6(F) J17.7(G) J17.8(H) J17.9(J) J17.10(K) J17.11(L) J17.12(M) J17.23(Z) J17.25(b) J17.26(c) J17.31(E) J17.33(G) J17.35(J) J17.40(P) J17.42(S) J17.49(Z) J17.51(b) J17.52(c) J17.58(F) J17.59(G) J17.60(H) J17.61(J) J17.64(M) J17.66(P) J17.75(Z) J17.77(b) J17.78(c) J17.84(F) J17.86(H) J17.101(Z) J17.103(b) J17.104(c) J17.109(E) J17.110(F) J17.111(G) J17.112(H) J17.113(J) J17.114(K) J17.135(E) J17.137(G) J17.139(J) J17.142(M) J17.146(S) J17.147(T) J17.151(X) J17.152(Y) J17.157(MT1) J17.158(MT2) J17.159(MT3) J17.160(MT4) J18.5(E) J18.6(F) J18.7(G) J18.8(H) J18.9(J) J18.10(K) J18.11(L) J18.12(M) J18.23(Z) J18.25(b) J18.26(c) J18.31(E) J18.33(G) J18.35(J) J18.40(P) J18.42(S) J18.49(Z) J18.51(b) J18.52(c) J18.58(F) J18.59(G) J18.60(H) J18.61(J) J18.64(M) J18.66(P) J18.75(Z) J18.77(b) J18.78(c) J18.84(F) J18.86(H) J18.101(Z) J18.103(b) J18.104(c) J18.109(E) J18.110(F) J18.111(G) J18.112(H) J18.113(J) J18.114(K) J18.135(E) J18.137(G) J18.139(J) J18.142(M) J18.146(S) J18.147(T) J18.151(X) J18.152(Y) J18.157(MT1) J18.158(MT2) J18.159(MT3) J18.160(MT4) R19.1 R20.2 R21.2 R22.1 R22.2 R23.2 R24.1 R24.2 R25.2 R26.2 R27.2 R28.1 R29.2 R36.1 R36.2 R41.1 R41.2 R47.2 R48.2 R49.2 R56.1 R57.1 R62.1 R63.1 R66.1 R86.1 R99.1 R101.1 R103.1 R103.2 R104.1 R104.2 R106.2 R116.1 R117.2 R118.2 R120.2 U1.1(VIN1) U1.2(GND) U1.6(VIN2) U1.7(PAD) U15.3(A) U15.5(A) U15.7(GND) U15.13(A) U16.6(Y) U16.7(GND) U16.8(Y) U16.12(Y) U16.14(VCC) U19.2(B) U19.7(GND) U19.8(Y) U19.13(C) U19.14(VCC) U20.2(Y) U20.3(A) U20.4(Y) U20.6(Y) U20.7(GND) U20.8(Y) U20.9(A) U20.14(VCC) U21.1(A) U21.7(GND) U21.14(VCC) XPH1.1(GND) XPH2.1(GND) XPH3.1(GND) XPH4.1(GND) XPH5.1(GND) XPH6.1(GND) XPH7.1(GND) XPH8.1(GND) XPH9.1(GND) ; also on sheet 1 2
GND_POWER: C53.2 C54.2 C58.2 C59.2 C60.2 C61.2 C62.2 C63.2 C64.2 C65.2 C67.2 C69.2 C70.2 C71.2 C72.2 C73.2 C74.2 C75.2 C79.2 C80.2 C81.2 C82.2 C83.2 C84.2 C85.2 C86.2 C87.2 C88.2 C91.2 C92.2 C93.2 C94.2 C95.2 C96.2 C97.2 C98.2 C101.2 C102.2 C103.2 C104.2 C105.2 C106.2 C107.2 C108.2 C112.2 C113.2 C114.2 C115.2 C116.2 C117.2 C120.2 C121.2 C122.2 C151.2 J11.5 J11.10 J11.11 J12.3 J13.3 J14.3 J15.3 J19.1 J19.2 R58.1 R68.1 R69.1 R105.1 R106.1 ; also on sheet 1
P3.3V: C23.1 C24.1 U1.4(VOUT) U1.5(VS) U15.14(P3.3V)
P48V: J19.3 ; also on sheet 1
1: S9.1 S10.1 S11.1 S12.1 S13.1 S14.1 S15.1 S16.1 S17.1 S18.1 S19.1 S20.1 S21.1 S22.1 S23.1 S24.1 S25.1 S26.1 S27.1 S28.1 S29.1 S30.1 S31.1 S32.1 S33.1 S34.1 S35.1 S36.1 S37.1 S38.1 S39.1 S40.1 SO5.1 SO6.1 SO7.1 SO8.1 SO9.1 SO10.1 SO11.1 SO12.1 SO13.1 SO14.1 SO15.1 SO16.1 SO17.1 SO18.1 SO19.1 SO20.1 ; also on sheet 1
69: J16.69(T)
70: J16.70(U)
71: J16.71(V)
72: J16.72(W)
A0: J16.39(N) U20.1(A) ; also on sheet 2
A2: J16.41(R) U20.5(A) ; also on sheet 2
BRAKE1_VMON: R67.2 ; also on sheet 2
BRAKE2_VMON: R64.2 ; also on sheet 2
BRAKE3_VMON: R102.2 ; also on sheet 2
BRAKE4_VMON: R85.2 ; also on sheet 2
CLK: U15.4(Y) ; also on sheet 2
DOUTB3: J16.30(D) R21.1 U15.9(A)
ENCB-3: J16.15
ENCB-4: J16.16
ENCI+1: J16.53(A)
ENCI+4: J16.56(D)
ENCI-1: J16.19
ENCI-2: J16.20
ENCI-3: J16.21
ENCI-4: J16.22
FAULT: J16.47(X) U20.10(Y)
FAULTn: J16.13 U20.11(A) ; also on sheet 1
MOTOR-1: J11.6 J12.1
MOTOR-2: J11.7 J13.1
MOTOR-3: J11.8 J14.1
MOTOR-4: J11.9 J15.1
OTW: J16.48(Y) U20.12(Y)
OTWn: J16.14 U20.13(A) ; also on sheet 1
POT3: J16.37(L) ; also on sheet 2
POT4: J16.4 ; also on sheet 2
PWM: U15.6(Y) U15.11(A) ; also on sheet 1
PWMn: U15.10(Y) ; also on sheet 1
RESETn: U15.8(Y) ; also on sheet 1
RST: U15.2(Y) ; also on sheet 2
SJ1_BRK_REL: J16.17 U19.12(Y)
SJ1_POT2: J16.85(G) ; also on sheet 2
SJ1_POT3: J16.136(F) ; also on sheet 2
SJ1_POT5: J16.87(J) ; also on sheet 2
SJ1_POT6: J16.138(H) ; also on sheet 2
SJ1_POT12: J16.140(K) ; also on sheet 2
SJ1_POT13: J16.18 J16.24 R25.1 U15.1(A) U19.6(Y) ; also on sheet 2
SJ1_POT14: J16.50(a) ; also on sheet 2
SJ1_POT15: J16.76(a) ; also on sheet 2
SJ1_POT16: J16.102(a) ; also on sheet 2
SJ1_SPARE1: C169.1 J16.92(P) R62.2 ; also on sheet 2
SJ1_SPARE2: C168.1 J16.118(P) R66.2 ; also on sheet 2
SJ2_BRAKE_PWR: C63.1 C64.1 C72.1 C86.1 C106.1 C115.1 J9.2(B) J9.3(C) J9.54(B) J9.55(C) J9.106(B) J9.107(C) J11.2 R59.1
SJ2_BRAKE_RTN: C73.1 C85.1 C95.1 C96.1 C105.1 C121.1 J9.28(B) J9.29(C) J9.80(B) J9.81(C) J9.132(B) J9.133(C) J13.2
SJ2_GND_SENSEn: J9.63(L) U19.5(C)
SJ2_POT1: J9.32(F) ; also on sheet 2
SJ2_POT2: J9.85(G) ; also on sheet 2
SJ2_POT3: J9.136(F) ; also on sheet 2
SJ2_POT4: J9.34(H) ; also on sheet 2
SJ2_POT5: J9.87(J) ; also on sheet 2
SJ2_POT6: J9.138(H) ; also on sheet 2
SJ2_POT11: J9.36(K) ; also on sheet 2
SJ2_POT12: J9.140(K) ; also on sheet 2
SJ2_POT13: J9.18(U) J9.24(a) ; also on sheet 2
SJ2_POT14: J9.50(a) ; also on sheet 2
SJ2_POT15: J9.76(a) ; also on sheet 2
SJ2_POT16: J9.102(a) ; also on sheet 2
SJ2_REL: J9.62(K) R117.1 U21.3(A)
SJ2_RELn: J9.65(N) R118.1 U19.4(B)
SJ2_SPARE1: C167.1 J9.92(P) R56.2 ; also on sheet 2
SJ2_SPARE2: C166.1 J9.118(P) R57.2 ; also on sheet 2
SJ3_BRAKE_PWR: C62.1 C70.1 C84.1 C104.1 C113.1 C114.1 J11.3 J17.2(B) J17.3(C) J17.54(B) J17.55(C) J17.106(B) J17.107(C) R98.1
SJ3_BRAKE_RTN: C61.1 C71.1 C83.1 C93.1 C94.1 C103.1 J14.2 J17.28(B) J17.29(C) J17.80(B) J17.81(C) J17.132(B) J17.133(C)
SJ3_GND_SENSEn: J17.63(L) U19.11(C)
SJ3_POT1: J17.32(F) ; also on sheet 2
SJ3_POT2: J17.85(G) ; also on sheet 2
SJ3_POT3: J17.136(F) ; also on sheet 2
SJ3_POT4: J17.34(H) ; also on sheet 2
SJ3_POT5: J17.87(J) ; also on sheet 2
SJ3_POT6: J17.138(H) ; also on sheet 2
SJ3_POT11: J17.36(K) ; also on sheet 2
SJ3_POT12: J17.140(K) ; also on sheet 2
SJ3_POT13: J17.18(U) J17.24(a) ; also on sheet 2
SJ3_POT14: J17.50(a) ; also on sheet 2
SJ3_POT15: J17.76(a) ; also on sheet 2
SJ3_POT16: J17.102(a) ; also on sheet 2
SJ3_PRESENTn: J16.45(V) J17.141(L)
SJ3_REL: J17.62(K) R47.1 U21.5(A)
SJ3_RELn: J17.65(N) R29.1 U19.10(B)
SJ3_SPARE1: C144.1 J17.92(P) R99.2 ; also on sheet 2
SJ3_SPARE2: C146.1 J17.118(P) R101.2 ; also on sheet 2
SJ4_BRAKE_PWR: C67.1 C79.1 C82.1 C91.1 C102.1 C112.1 J11.4 J18.2(B) J18.3(C) J18.54(B) J18.55(C) J18.106(B) J18.107(C) R70.1
SJ4_BRAKE_RTN: C59.1 C80.1 C81.1 C92.1 C101.1 C120.1 J15.2 J18.28(B) J18.29(C) J18.80(B) J18.81(C) J18.132(B) J18.133(C)
SJ4_GND_SENSEn: J18.63(L) U16.13(C)
SJ4_LIFT_MOTOR+: C69.1 J18.1(A) J18.53(A) J18.105(A) ; also on sheet 1
SJ4_LIFT_MOTOR-: C60.1 J18.27(A) J18.79(A) J18.131(A) ; also on sheet 1
SJ4_LM_DOWN_A: C171.1 J18.148(U) R48.1 U21.11(A)
SJ4_LM_DOWN_B: J18.144(P) R19.2 R20.1 U16.10(B)
SJ4_LM_GND_SENSEn: J18.150(W) R120.1 U16.5(C) U16.11(C)
SJ4_LM_UP_A: J18.145(R) R23.1 U21.13(A)
SJ4_LM_UP_B: C172.1 J18.149(V) R27.1 R28.2 U16.4(B)
SJ4_POT1: J18.32(F) ; also on sheet 2
SJ4_POT2: J18.85(G) ; also on sheet 2
SJ4_POT3: J18.136(F) ; also on sheet 2
SJ4_POT4: J18.34(H) ; also on sheet 2
SJ4_POT5: J18.87(J) ; also on sheet 2
SJ4_POT6: J18.138(H) ; also on sheet 2
SJ4_POT11: J18.36(K) ; also on sheet 2
SJ4_POT12: J18.140(K) ; also on sheet 2
SJ4_POT13: J18.18(U) J18.24(a) ; also on sheet 2
SJ4_POT14: J18.50(a) ; also on sheet 2
SJ4_POT15: J18.76(a) ; also on sheet 2
SJ4_POT16: J18.102(a) ; also on sheet 2
SJ4_PRESENTn: J16.46(W) J18.141(L)
SJ4_REL: J18.62(K) R49.1 U21.9(A)
SJ4_RELn: J18.65(N) R26.1 U16.2(B)
SJ4_SPARE1: C165.1 J16.43(T) J18.92(P) R116.2
SJ4_SPARE2: C164.1 J16.44(U) J18.118(P) R86.2
N7287158: U19.9(A) U21.6(Y)
N7735582: C53.1 R63.2 R67.1 R68.2
N7735586: C54.1 R58.2 R59.2 R64.1
N7735590: C151.1 R98.2 R102.1 R105.2
N7735594: C58.1 R69.2 R70.2 R85.1
N8605172: U16.3(A) U21.12(Y)
N8608912: U16.9(A) U21.10(Y)
N8612777: U16.1(A) U21.8(Y)
N8619490: U19.3(A) U21.4(Y)
N8626052: U19.1(A) U21.2(Y)

Not connected (* = marked no-connect by the designer): J9 1(A) 4(D) 13(N) 14(P) 15(R) 16(S) 17(T) 19(V) 20(W) 21(X) 22(Y) 27(A) 30(D) 37(L) 38(M) 39(N) 41(R) 43(T) 44(U) 45(V) 46(W) 47(X) 48(Y) 53(A) 56(D) 57(E) 67(R) 68(S) 69(T) 70(U) 71(V) 72(W) 73(X) 74(Y) 79(A) 82(D) 83(E) 88(K) 89(L) 90(M) 91(N) 93(R) 94(S) 95(T) 96(U) 97(V) 98(W) 99(X) 100(Y) 105(A) 108(D) 115(L) 116(M) 117(N) 119(R) 120(S) 121(T) 122(U) 123(V) 124(W) 125(X) 126(Y) 127(Z) 128(a) 129(b) 130(c) 131(A) 134(D) 143(N) 144(P) 145(R) 148(U) 149(V) 150(W) 153(Z) 154(a) 155(b) 156(c); J16 73(X) 74(Y) 79(A) 82(D) 83(E) 88(K) 89(L) 90(M) 91(N) 93(R) 94(S) 95(T) 96(U) 97(V) 98(W) 99(X) 100(Y) 105(A) 108(D) 115(L) 116(M) 117(N) 119(R) 120(S) 121(T) 122(U) 123(V) 124(W) 125(X) 126(Y) 127(Z) 128(a) 129(b) 130(c) 131(A) 134(D) 143(N) 144(P) 145(R) 148(U) 149(V) 150(W) 153(Z) 154(a) 155(b) 156(c); J17 1(A) 4(D) 13(N) 14(P) 15(R) 16(S) 17(T) 19(V) 20(W) 21(X) 22(Y) 27(A) 30(D) 37(L) 38(M) 39(N) 41(R) 43(T) 44(U) 45(V) 46(W) 47(X) 48(Y) 53(A) 56(D) 57(E) 67(R) 68(S) 69(T) 70(U) 71(V) 72(W) 73(X) 74(Y) 79(A) 82(D) 83(E) 88(K) 89(L) 90(M) 91(N) 93(R) 94(S) 95(T) 96(U) 97(V) 98(W) 99(X) 100(Y) 105(A) 108(D) 115(L) 116(M) 117(N) 119(R) 120(S) 121(T) 122(U) 123(V) 124(W) 125(X) 126(Y) 127(Z) 128(a) 129(b) 130(c) 131(A) 134(D) 143(N) 144(P) 145(R) 148(U) 149(V) 150(W) 153(Z) 154(a) 155(b) 156(c); J18 4(D) 13(N) 14(P) 15(R) 16(S) 17(T) 19(V) 20(W) 21(X) 22(Y) 30(D) 37(L) 38(M) 39(N) 41(R) 43(T) 44(U) 45(V) 46(W) 47(X) 48(Y) 56(D) 57(E) 67(R) 68(S) 69(T) 70(U) 71(V) 72(W) 73(X) 74(Y) 82(D) 83(E) 88(K) 89(L) 90(M) 91(N) 93(R) 94(S) 95(T) 96(U) 97(V) 98(W) 99(X) 100(Y) 108(D) 115(L) 116(M) 117(N) 119(R) 120(S) 121(T) 122(U) 123(V) 124(W) 125(X) 126(Y) 127(Z) 128(a) 129(b) 130(c) 134(D) 143(N) 153(Z) 154(a) 155(b) 156(c); U1 3(NC); U15 12(Y)

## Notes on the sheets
sheet 3
- MOTOR+1
- MOTOR-1
- MOTOR+2
- MOTOR-2
- MOTOR+3
- MOTOR-3
- MOTOR+4
- MOTOR-4
- 5V -> 3.3V Level Translation
- Digilent 424-VHDCI-CONNECTOR
- ENCA+1
- ENCA-1
- ENCA+2
- ENCA-2
- ENCA+3
- ENCA-3
- ENCA+4
- ENCA-4
- POSLIM3
- POSLIM1
- POSLIM4
- POSLIM2
- NEGLIM3
- NEGLIM4
- NEGLIM1
- NEGLIM2
- ENCB+1
- ENCB-1
- ENCB+2
- ENCB-2
- HOME3
- HOME4
- HOME1
- HOME2
